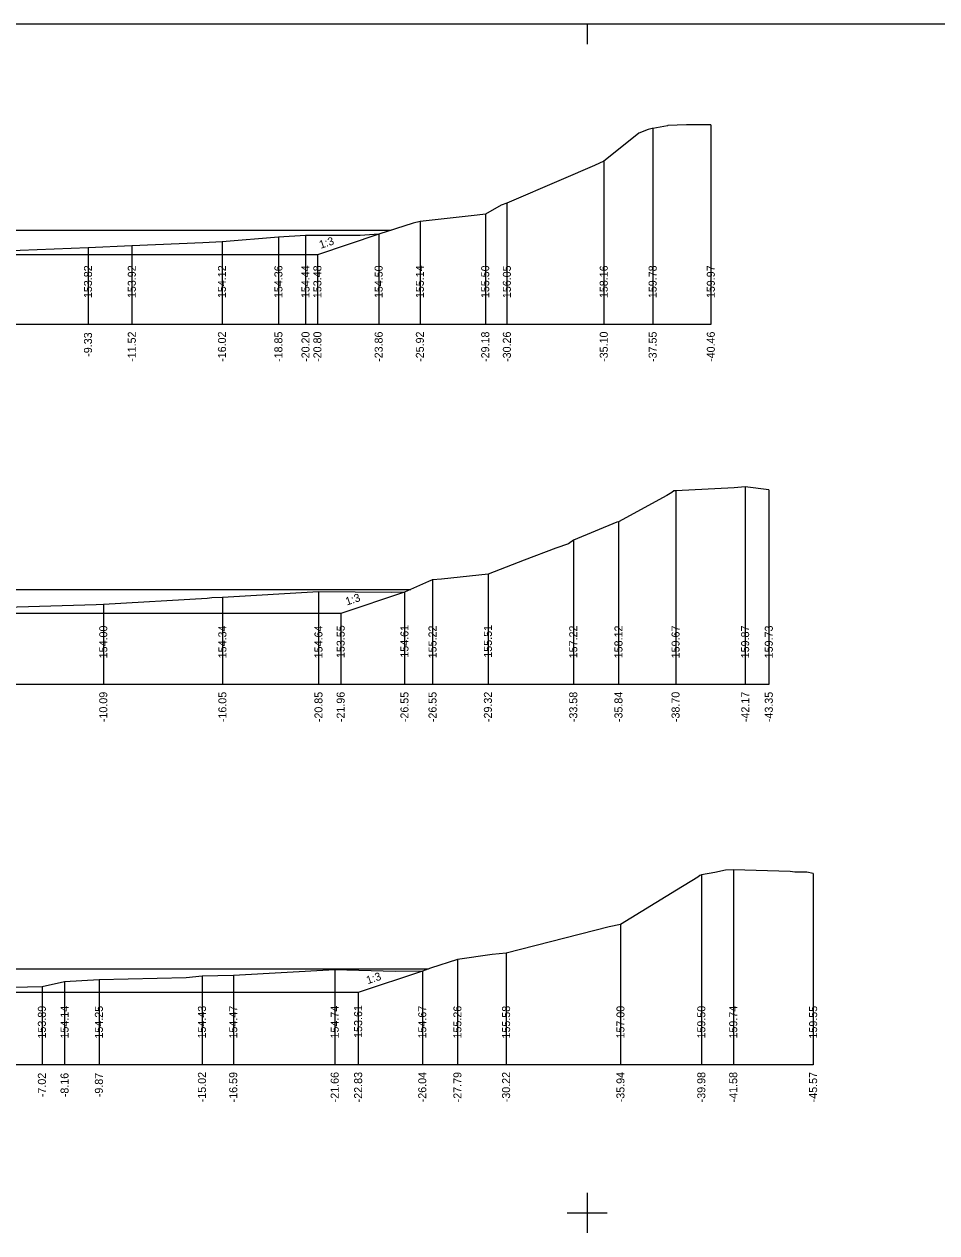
# Model space of a CAD drawing. Extents: x -582678 to -581845, y -1210354 to -1210235.
# Drawn here: x -582621.6 to -582576, y -1210295.7 to -1210235.3 of the extents above; entities that cross this region are included whole.
import ezdxf

# ---------------------------------------------------------------- set-up
doc = ezdxf.new("R2010")
doc.units = 0
for name, color, linetype in [('_N_popis', 7, 'Continuous'), ('_N_tučná', 7, 'Continuous'), ('_rámeček', 7, 'Continuous'), ('_S_hladina', 7, 'Continuous'), ('_S_popis', 7, 'Continuous'), ('_S_tenká', 7, 'Continuous'), ('_S_velmi_tenká', 7, 'Continuous')]:
    doc.layers.add(name, color=color, linetype=linetype)

msp = doc.modelspace()

# ---------------------------------------------------------------- linework, layer by layer
at = {"layer": '_N_popis'}
for points in [[(-582603.917, -1210245.791), (-582603.917, -1210250.291), (-582603.917, -1210250.291), (-582603.917, -1210250.291)], [(-582606.977, -1210246.811), (-582606.977, -1210250.291), (-582606.977, -1210250.291), (-582606.977, -1210250.291)], [(-582602.626, -1210263.678), (-582602.626, -1210268.291), (-582602.626, -1210268.291), (-582602.626, -1210268.291)], [(-582605.815, -1210264.741), (-582605.815, -1210268.291), (-582605.815, -1210268.291), (-582605.815, -1210268.291)], [(-582601.737, -1210282.613), (-582601.737, -1210287.291), (-582601.737, -1210287.291), (-582601.737, -1210287.291)], [(-582604.941, -1210283.681), (-582604.941, -1210287.291), (-582604.941, -1210287.291), (-582604.941, -1210287.291)]]:
    msp.add_lwpolyline(points, dxfattribs=at)
at = {"layer": '_N_tučná'}
for p, q in [((-582603.917, -1210245.791), (-582606.977, -1210246.811)), ((-582606.977, -1210246.811), (-582641.192, -1210246.811)), ((-582602.626, -1210263.678), (-582605.815, -1210264.741)), ((-582601.737, -1210282.613), (-582604.941, -1210283.681))]:
    msp.add_line(p, q, dxfattribs=at)
for points in [[(-582605.815, -1210264.741), (-582644.354, -1210264.741)], [(-582604.941, -1210283.681), (-582645.904, -1210283.681)]]:
    msp.add_lwpolyline(points, dxfattribs=at)
at = {"layer": '_rámeček'}
for p, q in [((-582467.502, -1210235.291), (-582677.502, -1210235.291)), ((-582593.502, -1210235.291), (-582593.502, -1210236.291)), ((-582593.502, -1210293.691), (-582593.502, -1210295.691)), ((-582594.502, -1210294.691), (-582592.502, -1210294.691))]:
    msp.add_line(p, q, dxfattribs=at)
at = {"layer": '_S_hladina'}
for points in [[(-582644.77, -1210245.591), (-582603.296, -1210245.591)], [(-582646.766, -1210263.541), (-582602.321, -1210263.541)], [(-582649.014, -1210282.501), (-582601.439, -1210282.501)]]:
    msp.add_lwpolyline(points, dxfattribs=at)
at = {"layer": '_S_tenká'}
for p, q in [((-582587.316, -1210250.291), (-582660.294, -1210250.291)), ((-582584.418, -1210268.291), (-582662.484, -1210268.291)), ((-582582.203, -1210287.291), (-582664.065, -1210287.291))]:
    msp.add_line(p, q, dxfattribs=at)
for points in [[(-582587.316, -1210240.32), (-582588.542, -1210240.322), (-582589.475, -1210240.361), (-582589.489, -1210240.364), (-582590.223, -1210240.51), (-582590.259, -1210240.499), (-582590.452, -1210240.552), (-582590.925, -1210240.744), (-582591.017, -1210240.816), (-582592.667, -1210242.13), (-582593.143, -1210242.352), (-582594.801, -1210243.067), (-582597.509, -1210244.237), (-582597.804, -1210244.329), (-582598.59, -1210244.788), (-582599.003, -1210244.837), (-582601.856, -1210245.148), (-582602.196, -1210245.237), (-582603.917, -1210245.791), (-582604.851, -1210245.857), (-582607.572, -1210245.848), (-582608.925, -1210245.934), (-582611.748, -1210246.172), (-582612.714, -1210246.223), (-582616.253, -1210246.371), (-582618.443, -1210246.469), (-582622.691, -1210246.633)], [(-582584.418, -1210258.56), (-582585.6, -1210258.416), (-582586.154, -1210258.454), (-582589.077, -1210258.617), (-582589.168, -1210258.613), (-582589.274, -1210258.691), (-582589.527, -1210258.845), (-582591.93, -1210260.168), (-582592.013, -1210260.183), (-582594.19, -1210261.072), (-582594.44, -1210261.26), (-582595.066, -1210261.478), (-582596.648, -1210262.08), (-582598.456, -1210262.778), (-582600.782, -1210263.019), (-582601.224, -1210263.063), (-582601.427, -1210263.139), (-582602.626, -1210263.678), (-582603.259, -1210263.686), (-582606.923, -1210263.653), (-582611.726, -1210263.946), (-582612.253, -1210263.959), (-582612.49, -1210263.984), (-582617.679, -1210264.292), (-582618.037, -1210264.313), (-582624.278, -1210264.498)], [(-582582.203, -1210277.74), (-582582.526, -1210277.661), (-582583.119, -1210277.667), (-582583.35, -1210277.639), (-582586.195, -1210277.551), (-582586.58, -1210277.564), (-582587.129, -1210277.684), (-582587.791, -1210277.794), (-582587.863, -1210277.84), (-582587.975, -1210277.918), (-582589.039, -1210278.561), (-582591.832, -1210280.291), (-582592.402, -1210280.401), (-582597.548, -1210281.714), (-582598.25, -1210281.786), (-582599.98, -1210282.03), (-582601.335, -1210282.462), (-582601.737, -1210282.613), (-582603.101, -1210282.628), (-582606.112, -1210282.549), (-582611.183, -1210282.825), (-582612.748, -1210282.86), (-582613.535, -1210282.94), (-582617.898, -1210283.046), (-582619.616, -1210283.154), (-582620.747, -1210283.397), (-582622.964, -1210283.447)]]:
    msp.add_lwpolyline(points, dxfattribs=at)
at = {"layer": '_S_velmi_tenká'}
for points in [[(-582590.223, -1210240.51), (-582590.223, -1210250.291), (-582590.223, -1210250.291), (-582590.223, -1210250.291)], [(-582587.316, -1210240.32), (-582587.316, -1210250.291), (-582587.316, -1210250.291), (-582587.316, -1210250.291)], [(-582592.667, -1210242.13), (-582592.667, -1210250.291), (-582592.667, -1210250.291), (-582592.667, -1210250.291)], [(-582597.509, -1210244.237), (-582597.509, -1210250.291), (-582597.509, -1210250.291), (-582597.509, -1210250.291)], [(-582598.59, -1210244.788), (-582598.59, -1210250.291), (-582598.59, -1210250.291), (-582598.59, -1210250.291)], [(-582601.856, -1210245.148), (-582601.856, -1210250.291), (-582601.856, -1210250.291), (-582601.856, -1210250.291)], [(-582611.748, -1210246.172), (-582611.748, -1210250.291), (-582611.748, -1210250.291), (-582611.748, -1210250.291)], [(-582608.925, -1210245.934), (-582608.925, -1210250.291), (-582608.925, -1210250.291), (-582608.925, -1210250.291)], [(-582607.572, -1210245.848), (-582607.572, -1210250.291), (-582607.572, -1210250.291), (-582607.572, -1210250.291)], [(-582618.443, -1210246.469), (-582618.443, -1210250.291), (-582618.443, -1210250.291), (-582618.443, -1210250.291)], [(-582616.253, -1210246.371), (-582616.253, -1210250.291), (-582616.253, -1210250.291), (-582616.253, -1210250.291)], [(-582589.077, -1210258.617), (-582589.077, -1210268.291), (-582589.077, -1210268.291), (-582589.077, -1210268.291)], [(-582585.6, -1210258.416), (-582585.6, -1210268.291), (-582585.6, -1210268.291), (-582585.6, -1210268.291)], [(-582584.418, -1210258.56), (-582584.418, -1210268.291), (-582584.418, -1210268.291), (-582584.418, -1210268.291)], [(-582591.93, -1210260.168), (-582591.93, -1210268.291), (-582591.93, -1210268.291), (-582591.93, -1210268.291)], [(-582594.19, -1210261.072), (-582594.19, -1210268.291), (-582594.19, -1210268.291), (-582594.19, -1210268.291)], [(-582601.224, -1210263.019), (-582601.224, -1210268.291), (-582601.224, -1210268.291), (-582601.224, -1210268.291)], [(-582598.456, -1210262.778), (-582598.456, -1210268.291), (-582598.456, -1210268.291), (-582598.456, -1210268.291)], [(-582606.923, -1210263.653), (-582606.923, -1210268.291), (-582606.923, -1210268.291), (-582606.923, -1210268.291)], [(-582617.679, -1210264.292), (-582617.679, -1210268.291), (-582617.679, -1210268.291), (-582617.679, -1210268.291)], [(-582611.726, -1210263.946), (-582611.726, -1210268.291), (-582611.726, -1210268.291), (-582611.726, -1210268.291)], [(-582586.195, -1210277.551), (-582586.195, -1210287.291), (-582586.195, -1210287.291), (-582586.195, -1210287.291)], [(-582587.791, -1210277.794), (-582587.791, -1210287.291), (-582587.791, -1210287.291), (-582587.791, -1210287.291)], [(-582582.203, -1210277.74), (-582582.203, -1210287.291), (-582582.203, -1210287.291), (-582582.203, -1210287.291)], [(-582591.832, -1210280.291), (-582591.832, -1210287.291), (-582591.832, -1210287.291), (-582591.832, -1210287.291)], [(-582597.548, -1210281.714), (-582597.548, -1210287.291), (-582597.548, -1210287.291), (-582597.548, -1210287.291)], [(-582599.98, -1210282.03), (-582599.98, -1210287.291), (-582599.98, -1210287.291), (-582599.98, -1210287.291)], [(-582617.898, -1210283.046), (-582617.898, -1210287.291), (-582617.898, -1210287.291), (-582617.898, -1210287.291)], [(-582612.748, -1210282.86), (-582612.748, -1210287.291), (-582612.748, -1210287.291), (-582612.748, -1210287.291)], [(-582611.183, -1210282.825), (-582611.183, -1210287.291), (-582611.183, -1210287.291), (-582611.183, -1210287.291)], [(-582606.112, -1210282.549), (-582606.112, -1210287.291), (-582606.112, -1210287.291), (-582606.112, -1210287.291)], [(-582620.747, -1210283.397), (-582620.747, -1210287.291), (-582620.747, -1210287.291), (-582620.747, -1210287.291)], [(-582619.616, -1210283.154), (-582619.616, -1210287.291), (-582619.616, -1210287.291), (-582619.616, -1210287.291)]]:
    msp.add_lwpolyline(points, dxfattribs=at)

# ---------------------------------------------------------------- texts
at = {"layer": '_N_popis'}
for s, rotation, p in [('1:3', 18.43495, (-582606.82, -1210246.519)), ('153.48', 90, (-582606.784, -1210248.982)), ('154.50', 90, (-582603.723, -1210248.981)), ('-20.80', 90, (-582606.784, -1210252.168)), ('-23.86', 90, (-582603.723, -1210252.169)), ('1:3', 18.43495, (-582605.506, -1210264.343)), ('153.55', 90, (-582605.622, -1210266.967)), ('154.61', 90, (-582602.433, -1210266.949)), ('-21.96', 90, (-582605.622, -1210270.169)), ('-26.55', 90, (-582602.433, -1210270.171)), ('1:3', 18.43495, (-582604.465, -1210283.269)), ('153.61', 90, (-582604.748, -1210285.949)), ('154.67', 90, (-582601.544, -1210285.981)), ('-22.83', 90, (-582604.748, -1210289.169)), ('-26.04', 90, (-582601.544, -1210289.168))]:
    msp.add_text(s, height=0.4, rotation=rotation, dxfattribs=at).set_placement(p)
at = {"layer": '_S_popis'}
for s, p in [('153.82', (-582618.25, -1210248.98)), ('153.92', (-582616.06, -1210248.98)), ('154.12', (-582611.555, -1210248.98)), ('154.36', (-582608.732, -1210248.981)), ('154.44', (-582607.379, -1210248.981)), ('155.14', (-582601.663, -1210248.981)), ('155.50', (-582598.397, -1210248.981)), ('156.05', (-582597.316, -1210248.982)), ('158.16', (-582592.474, -1210248.981)), ('159.78', (-582590.03, -1210248.982)), ('159.97', (-582587.123, -1210248.981)), ('-9.33', (-582618.25, -1210251.914)), ('-11.52', (-582616.06, -1210252.166)), ('-16.02', (-582611.555, -1210252.166)), ('-18.85', (-582608.732, -1210252.171)), ('-20.20', (-582607.379, -1210252.168)), ('-25.92', (-582601.663, -1210252.166)), ('-29.18', (-582598.397, -1210252.17)), ('-30.26', (-582597.316, -1210252.169)), ('-35.10', (-582592.474, -1210252.168)), ('-37.55', (-582590.03, -1210252.171)), ('-40.46', (-582587.123, -1210252.169)), ('154.00', (-582617.486, -1210266.981)), ('154.34', (-582611.533, -1210266.981)), ('154.64', (-582606.73, -1210266.981)), ('155.22', (-582601.031, -1210266.98)), ('155.51', (-582598.263, -1210266.949)), ('157.22', (-582593.997, -1210266.98)), ('158.12', (-582591.737, -1210266.98)), ('159.67', (-582588.884, -1210266.981)), ('159.87', (-582585.407, -1210266.981)), ('159.73', (-582584.225, -1210266.981)), ('-10.09', (-582617.486, -1210270.17)), ('-16.05', (-582611.533, -1210270.171)), ('-20.85', (-582606.73, -1210270.171)), ('-26.55', (-582601.031, -1210270.171)), ('-29.32', (-582598.263, -1210270.166)), ('-33.58', (-582593.997, -1210270.17)), ('-35.84', (-582591.737, -1210270.168)), ('-38.70', (-582588.884, -1210270.168)), ('-42.17', (-582585.4, -1210270.169)), ('-43.35', (-582584.225, -1210270.171)), ('153.89', (-582620.554, -1210285.982)), ('154.14', (-582619.422, -1210285.981)), ('154.25', (-582617.705, -1210285.982)), ('154.43', (-582612.555, -1210285.981)), ('154.47', (-582610.99, -1210285.981)), ('154.74', (-582605.919, -1210285.981)), ('155.26', (-582599.787, -1210285.981)), ('155.58', (-582597.354, -1210285.982)), ('157.00', (-582591.639, -1210285.981)), ('159.50', (-582587.598, -1210285.981)), ('159.74', (-582586.002, -1210285.981)), ('159.55', (-582582.01, -1210285.982)), ('-7.02', (-582620.554, -1210288.911)), ('-8.16', (-582619.422, -1210288.914)), ('-9.87', (-582617.705, -1210288.914)), ('-15.02', (-582612.555, -1210289.166)), ('-16.59', (-582610.99, -1210289.17)), ('-21.66', (-582605.919, -1210289.169)), ('-27.79', (-582599.787, -1210289.17)), ('-30.22', (-582597.354, -1210289.166)), ('-35.94', (-582591.639, -1210289.168)), ('-39.98', (-582587.598, -1210289.17)), ('-41.58', (-582586.002, -1210289.17)), ('-45.57', (-582582.01, -1210289.169))]:
    msp.add_text(s, height=0.4, rotation=90, dxfattribs=at).set_placement(p)

doc.saveas('drawing.dxf')
